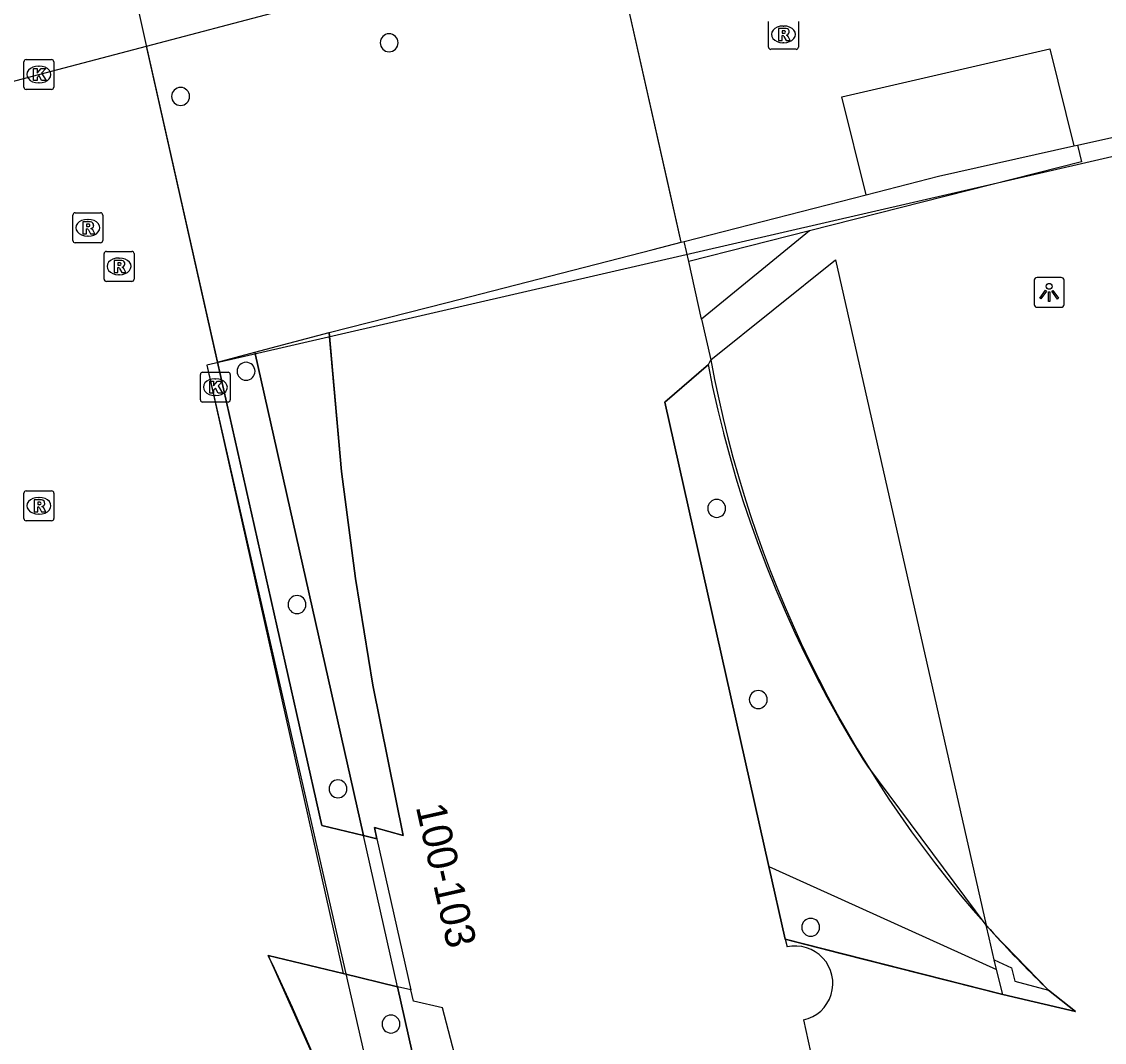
# Model space of a CAD drawing. Extents: x 160806 to 161707, y 383697 to 384148.
# Drawn here: x 161397.72 to 161433.94, y 383896.21 to 383930.37 of the extents above; entities that cross this region are included whole.
import ezdxf

# ---------------------------------------------------------------- set-up
doc = ezdxf.new("R2010")
doc.units = 0
for name, color, linetype in [('IMGEO_Hek', 7, 'Continuous'), ('IMGEO_Kolk', 7, 'Continuous'), ('IMGEO_Lichtpunt', 7, 'Continuous'), ('IMGEO_Lijnafwatering', 7, 'Continuous'), ('IMGEO_Muur', 7, 'Continuous'), ('IMGEO_OVBaan_gesloten', 7, 'Continuous'), ('IMGEO_Pand', 7, 'Continuous'), ('IMGEO_Pand_nummerreeks', 7, 'Continuous'), ('IMGEO_Pand_overbouw', 7, 'Continuous'), ('IMGEO_Rijbaan_lokaal_open', 7, 'Continuous'), ('IMGEO_Rioolput', 7, 'Continuous'), ('IMGEO_Voetpad_open', 7, 'Continuous')]:
    doc.layers.add(name, color=color, linetype=linetype)

msp = doc.modelspace()

# ---------------------------------------------------------------- linework, layer by layer
at = {"layer": 'IMGEO_Hek'}
for points in [[(161405.527, 383919.308), (161408.013, 383919.96)], [(161409.16, 383903.134), (161405.527, 383919.308)], [(161410.296, 383898.071), (161409.16, 383903.134)], [(161418.7, 383860.601), (161410.296, 383898.071)]]:
    msp.add_lwpolyline(points, dxfattribs=at)
at = {"layer": 'IMGEO_Kolk'}
for p, q in [((161397.8, 383928.172), (161397.8, 383929.024)), ((161397.875, 383929.098), (161398.727, 383929.098)), ((161398.288, 383928.878), (161398.313, 383928.878)), ((161398.801, 383929.024), (161398.801, 383928.172)), ((161398.311, 383928.318), (161398.286, 383928.318)), ((161398.727, 383928.098), (161397.875, 383928.098)), ((161403.703, 383917.71), (161403.703, 383918.562)), ((161403.778, 383918.636), (161404.63, 383918.636)), ((161404.191, 383918.416), (161404.216, 383918.416)), ((161404.704, 383918.562), (161404.704, 383917.71)), ((161404.63, 383917.636), (161403.778, 383917.636)), ((161404.214, 383917.856), (161404.189, 383917.856))]:
    msp.add_line(p, q, dxfattribs=at)
for points in [[(161397.8, 383928.172), (161397.8, 383929.024)], [(161397.875, 383929.098), (161398.727, 383929.098)], [(161398.801, 383929.024), (161398.801, 383928.172)], [(161398.121, 383928.798), (161398.244, 383928.798), (161398.244, 383928.647), (161398.374, 383928.798), (161398.538, 383928.798), (161398.392, 383928.647), (161398.545, 383928.398), (161398.393, 383928.398), (161398.308, 383928.562), (161398.244, 383928.495), (161398.244, 383928.398), (161398.121, 383928.398), (161398.121, 383928.798)], [(161398.727, 383928.098), (161397.875, 383928.098)], [(161403.703, 383917.71), (161403.703, 383918.562)], [(161403.778, 383918.636), (161404.63, 383918.636)], [(161404.704, 383918.562), (161404.704, 383917.71)], [(161404.024, 383918.336), (161404.147, 383918.336), (161404.147, 383918.185), (161404.277, 383918.336), (161404.441, 383918.336), (161404.295, 383918.185), (161404.448, 383917.936), (161404.296, 383917.936), (161404.211, 383918.1), (161404.147, 383918.033), (161404.147, 383917.936), (161404.024, 383917.936), (161404.024, 383918.336)], [(161404.63, 383917.636), (161403.778, 383917.636)]]:
    msp.add_lwpolyline(points, dxfattribs=at)
for centre, start, end in [((161397.877, 383929.022), 91.552, 178.448), ((161397.877, 383929.022), 91.552, 178.448), ((161398.725, 383929.022), 1.552, 88.448), ((161398.725, 383929.022), 1.552, 88.448), ((161397.877, 383928.174), 181.552, 268.448), ((161397.877, 383928.174), 181.552, 268.448), ((161398.725, 383928.174), 271.552, 358.448), ((161398.725, 383928.174), 271.552, 358.448), ((161403.78, 383918.56), 91.552, 178.448), ((161403.78, 383918.56), 91.552, 178.448), ((161404.628, 383918.56), 1.552, 88.448), ((161404.628, 383918.56), 1.552, 88.448), ((161403.78, 383917.712), 181.552, 268.448), ((161403.78, 383917.712), 181.552, 268.448), ((161404.628, 383917.712), 271.552, 358.448), ((161404.628, 383917.712), 271.552, 358.448)]:
    msp.add_arc(centre, 0.0765, start, end, dxfattribs=at)
for centre, major_axis, ratio, start_param, end_param in [((161398.287, 383928.598), (-0.387, 0.002), 0.722429, 4.712389, 7.853982), ((161398.312, 383928.598), (-0.39, 0.002), 0.717154, 1.570796, 4.712389), ((161404.19, 383918.136), (-0.387, 0.002), 0.722429, 4.712389, 7.853982), ((161404.215, 383918.136), (-0.39, 0.002), 0.717154, 1.570796, 4.712389)]:
    msp.add_ellipse(centre, major_axis=major_axis, ratio=ratio, start_param=start_param, end_param=end_param, dxfattribs=at)
at = {"layer": 'IMGEO_Lichtpunt'}
for p, q in [((161431.595, 383921.712), (161431.595, 383920.905)), ((161431.595, 383921.712), (161431.595, 383920.905)), ((161432.497, 383921.807), (161431.689, 383921.807)), ((161432.497, 383921.807), (161431.689, 383921.807)), ((161432.591, 383920.905), (161432.591, 383921.712)), ((161432.591, 383920.905), (161432.591, 383921.712)), ((161431.689, 383920.811), (161432.497, 383920.811)), ((161431.689, 383920.811), (161432.497, 383920.811))]:
    msp.add_line(p, q, dxfattribs=at)
for points in [[(161431.969, 383921.376), (161432.008, 383921.348), (161431.82, 383921.086), (161431.782, 383921.113), (161431.969, 383921.376)], [(161432.071, 383921.328), (161432.118, 383921.328), (161432.118, 383921.006), (161432.071, 383921.006), (161432.071, 383921.328)], [(161432.181, 383921.348), (161432.219, 383921.375), (161432.406, 383921.113), (161432.367, 383921.085), (161432.181, 383921.348)]]:
    msp.add_lwpolyline(points, dxfattribs=at)
msp.add_circle((161432.094, 383921.51), 0.0994, dxfattribs=at)
for centre, start, end in [((161431.689, 383921.712), 90, 180), ((161431.689, 383921.712), 90, 180), ((161432.497, 383921.712), 0, 90), ((161432.497, 383921.712), 0, 90), ((161431.689, 383920.905), 180, 270), ((161431.689, 383920.905), 180, 270), ((161432.497, 383920.905), 270, 0), ((161432.497, 383920.905), 270, 360)]:
    msp.add_arc(centre, 0.0946, start, end, dxfattribs=at)
at = {"layer": 'IMGEO_Lijnafwatering'}
msp.add_lwpolyline([(161403.923, 383918.874), (161408.481, 383898.51)], dxfattribs=at)
at = {"layer": 'IMGEO_Muur'}
for points in [[(161433.038, 383926.234), (161439.383, 383927.651)], [(161433.038, 383926.234), (161433.18, 383925.675), (161424.076, 383923.368)], [(161425.968, 383924.573), (161428.39, 383925.195), (161432.923, 383926.208)], [(161432.923, 383926.208), (161433.038, 383926.234)], [(161419.888, 383923.011), (161425.968, 383924.573)], [(161424.076, 383923.368), (161420.037, 383922.345)]]:
    msp.add_lwpolyline(points, dxfattribs=at)
at = {"layer": 'IMGEO_OVBaan_gesloten'}
for points in [[(161401.899, 383929.545), (161406.303, 383930.704), (161406.292, 383930.768), (161411.273, 383932.069), (161417.389, 383933.655)], [(161396.1, 383928.014), (161398.301, 383928.598), (161401.899, 383929.545)]]:
    msp.add_lwpolyline(points, dxfattribs=at)
at = {"layer": 'IMGEO_Pand'}
for points in [[(161408.013, 383919.96), (161411.952, 383920.972), (161418.849, 383922.744), (161419.786, 383922.985)], [(161419.786, 383922.985), (161419.888, 383923.011)], [(161420.037, 383922.345), (161419.888, 383923.011)], [(161420.469, 383920.416), (161420.037, 383922.345)], [(161420.469, 383920.416), (161420.775, 383919.046)], [(161408.013, 383919.96), (161408.426, 383915.311), (161408.889, 383911.729), (161409.47, 383908.166), (161410.484, 383903.138), (161409.523, 383903.401), (161409.607, 383903.025)], [(161422.721, 383902.1), (161419.234, 383917.635), (161420.694, 383918.894), (161420.775, 383919.046)], [(161409.607, 383903.025), (161410.742, 383897.964)], [(161423.268, 383899.662), (161422.721, 383902.1)], [(161423.268, 383899.662), (161423.327, 383899.403)], [(161424.012, 383864.925), (161421.322, 383870.26), (161418.342, 383876.968), (161415.742, 383883.762), (161414.609, 383887.201), (161413.557, 383890.652), (161411.798, 383897.366), (161410.827, 383897.586), (161410.742, 383897.964)], [(161423.875, 383896.96), (161424.112, 383895.898)]]:
    msp.add_lwpolyline(points, dxfattribs=at)
for centre, radius, start, end in [((161410.016, 383929.66), 0.3, 90, 270), ((161410.016, 383929.66), 0.3, 270, 90), ((161403.04, 383927.864), 0.3, 90, 270), ((161403.04, 383927.864), 0.3, 270, 90), ((161405.23, 383918.667), 0.3, 90, 270), ((161405.23, 383918.667), 0.3, 270, 90), ((161420.973, 383914.079), 0.3, 90, 270), ((161420.973, 383914.079), 0.3, 270, 90), ((161406.935, 383910.86), 0.3, 90, 270), ((161406.935, 383910.86), 0.3, 270, 90), ((161422.364, 383907.682), 0.3, 90, 270), ((161422.364, 383907.682), 0.3, 270, 90), ((161408.305, 383904.694), 0.3, 90, 270), ((161408.305, 383904.694), 0.3, 270, 90), ((161424.117, 383900.061), 0.3, 90, 270), ((161424.117, 383900.061), 0.3, 270, 90), ((161423.607, 383898.183), 1.252, 282.3385, 102.9475), ((161410.078, 383896.824), 0.3, 90, 270), ((161410.078, 383896.824), 0.3, 270, 90)]:
    msp.add_arc(centre, radius, start, end, dxfattribs=at)
at = {"layer": 'IMGEO_Pand_overbouw'}
for points in [[(161576.544, 383863.524), (161556.299, 383953.974), (161403.923, 383918.874), (161417.58, 383859.039), (161456.542, 383836.683)], [(161410.484, 383903.138), (161409.47, 383908.166), (161408.889, 383911.729), (161408.426, 383915.311), (161408.026, 383919.819), (161408.013, 383919.96), (161411.952, 383920.972), (161418.849, 383922.744), (161419.786, 383922.985), (161419.437, 383924.536), (161417.522, 383933.062), (161417.086, 383935.004), (161401.461, 383931.49), (161401.894, 383929.568), (161407.767, 383903.471), (161409.16, 383903.134), (161409.607, 383903.025), (161409.523, 383903.401)], [(161432.972, 383897.242), (161432.074, 383897.956), (161430.247, 383899.844), (161429.992, 383900.129), (161426.025, 383905.451), (161425.874, 383905.688), (161425.459, 383906.371), (161425.058, 383907.061), (161424.671, 383907.76), (161424.299, 383908.467), (161423.941, 383909.18), (161423.598, 383909.9), (161423.271, 383910.627), (161422.958, 383911.359), (161422.661, 383912.097), (161422.38, 383912.839), (161422.114, 383913.586), (161421.863, 383914.337), (161421.629, 383915.091), (161421.41, 383915.848), (161421.215, 383916.58), (161421.208, 383916.607), (161421.021, 383917.368), (161420.849, 383918.131), (161420.694, 383918.894), (161419.234, 383917.635), (161422.721, 383902.1), (161423.268, 383899.662), (161425.13, 383899.181), (161430.54, 383897.812)], [(161405.973, 383899.115), (161408.052, 383894.445), (161409.909, 383889.683), (161411.541, 383884.838), (161412.522, 383881.497), (161413.685, 383876.957), (161417.567, 383859.679), (161418.7, 383860.601), (161424.012, 383864.925), (161421.322, 383870.26), (161418.342, 383876.968), (161415.742, 383883.762), (161414.609, 383887.201), (161413.557, 383890.652), (161411.798, 383897.366), (161410.827, 383897.586), (161410.742, 383897.964), (161410.296, 383898.071), (161408.481, 383898.51)]]:
    msp.add_lwpolyline(points, close=True, dxfattribs=at)
at = {"layer": 'IMGEO_Rijbaan_lokaal_open'}
for points in [[(161419.786, 383922.985), (161417.522, 383933.062), (161417.389, 383933.655)], [(161404.279, 383918.971), (161401.899, 383929.545)], [(161425.968, 383924.573), (161425.161, 383927.855), (161432.12, 383929.454), (161432.923, 383926.208)], [(161433.038, 383926.234), (161439.383, 383927.651)], [(161405.527, 383919.308), (161408.013, 383919.96)], [(161404.279, 383918.971), (161405.527, 383919.308)], [(161409.16, 383903.134), (161407.767, 383903.471), (161404.279, 383918.971)], [(161410.296, 383898.071), (161409.16, 383903.134)], [(161405.973, 383899.115), (161408.481, 383898.51), (161410.296, 383898.071)]]:
    msp.add_lwpolyline(points, dxfattribs=at)
msp.add_arc((161307.805, 383852.606), 108.628, 17.2609, 25.35045, dxfattribs=at)
at = {"layer": 'IMGEO_Rioolput'}
for p, q in [((161422.704, 383929.515), (161422.704, 383930.367)), ((161423.705, 383930.367), (161423.705, 383929.515)), ((161423.192, 383930.221), (161423.217, 383930.221)), ((161423.215, 383929.661), (161423.19, 383929.661)), ((161423.631, 383929.441), (161422.779, 383929.441)), ((161399.437, 383923.044), (161399.437, 383923.896)), ((161399.512, 383923.97), (161400.364, 383923.97)), ((161400.438, 383923.896), (161400.438, 383923.044)), ((161399.925, 383923.75), (161399.95, 383923.75)), ((161399.948, 383923.19), (161399.923, 383923.19)), ((161400.364, 383922.97), (161399.512, 383922.97)), ((161400.482, 383921.751), (161400.482, 383922.603)), ((161400.557, 383922.677), (161401.409, 383922.677)), ((161400.97, 383922.457), (161400.995, 383922.457)), ((161401.483, 383922.603), (161401.483, 383921.751)), ((161401.409, 383921.677), (161400.557, 383921.677)), ((161400.993, 383921.897), (161400.968, 383921.897)), ((161397.801, 383913.74), (161397.801, 383914.592)), ((161397.876, 383914.666), (161398.728, 383914.666)), ((161398.289, 383914.446), (161398.314, 383914.446)), ((161398.802, 383914.592), (161398.802, 383913.74)), ((161398.728, 383913.666), (161397.876, 383913.666)), ((161398.312, 383913.886), (161398.287, 383913.886))]:
    msp.add_line(p, q, dxfattribs=at)
for points in [[(161422.704, 383929.515), (161422.704, 383930.367)], [(161423.705, 383930.367), (161423.705, 383929.515)], [(161423.293, 383930.139), (161423.041, 383930.141), (161423.041, 383929.741)], [(161423.219, 383930.06), (161423.165, 383930.06), (161423.165, 383929.979)], [(161423.165, 383929.979), (161423.217, 383929.979)], [(161423.041, 383929.741), (161423.165, 383929.741), (161423.165, 383929.903), (161423.176, 383929.903)], [(161423.223, 383929.874), (161423.294, 383929.741), (161423.434, 383929.741), (161423.369, 383929.867)], [(161423.631, 383929.441), (161422.779, 383929.441)], [(161399.437, 383923.044), (161399.437, 383923.896)], [(161399.512, 383923.97), (161400.364, 383923.97)], [(161400.438, 383923.896), (161400.438, 383923.044)], [(161400.026, 383923.668), (161399.774, 383923.67), (161399.774, 383923.27)], [(161399.774, 383923.27), (161399.898, 383923.27), (161399.898, 383923.432), (161399.909, 383923.432)], [(161399.952, 383923.589), (161399.898, 383923.589), (161399.898, 383923.508)], [(161399.898, 383923.508), (161399.95, 383923.508)], [(161399.956, 383923.403), (161400.027, 383923.27), (161400.167, 383923.27), (161400.102, 383923.396)], [(161400.364, 383922.97), (161399.512, 383922.97)], [(161400.482, 383921.751), (161400.482, 383922.603)], [(161400.557, 383922.677), (161401.409, 383922.677)], [(161401.071, 383922.375), (161400.819, 383922.377), (161400.819, 383921.977)], [(161401.483, 383922.603), (161401.483, 383921.751)], [(161400.819, 383921.977), (161400.943, 383921.977), (161400.943, 383922.139), (161400.954, 383922.139)], [(161400.997, 383922.296), (161400.943, 383922.296), (161400.943, 383922.215)], [(161400.943, 383922.215), (161400.995, 383922.215)], [(161401.001, 383922.11), (161401.072, 383921.977), (161401.212, 383921.977), (161401.147, 383922.103)], [(161401.409, 383921.677), (161400.557, 383921.677)], [(161397.801, 383913.74), (161397.801, 383914.592)], [(161397.876, 383914.666), (161398.728, 383914.666)], [(161398.802, 383914.592), (161398.802, 383913.74)], [(161398.39, 383914.364), (161398.138, 383914.366), (161398.138, 383913.966)], [(161398.138, 383913.966), (161398.262, 383913.966), (161398.262, 383914.128), (161398.273, 383914.128)], [(161398.316, 383914.285), (161398.262, 383914.285), (161398.262, 383914.204)], [(161398.262, 383914.204), (161398.314, 383914.204)], [(161398.32, 383914.099), (161398.391, 383913.966), (161398.531, 383913.966), (161398.466, 383914.092)], [(161398.728, 383913.666), (161397.876, 383913.666)]]:
    msp.add_lwpolyline(points, dxfattribs=at)
for centre, radius, start, end in [((161423.201, 383930.168), 0.19, 274.7715, 282.9687), ((161423.225, 383929.964), 0.0964, 77.0061, 93.1865), ((161423.239, 383930.021), 0.0378, 276.6634, 79.6772), ((161423.292, 383930.029), 0.109, 350.3612, 89.416), ((161423.29, 383930.029), 0.112, 277.5842, 350.9817), ((161423.175, 383929.85), 0.0533, 26.0293, 88.6989), ((161423.274, 383929.814), 0.108, 29.5134, 73.7905), ((161422.781, 383929.517), 0.0765, 181.552, 268.448), ((161422.781, 383929.517), 0.0765, 181.552, 268.448), ((161423.629, 383929.517), 0.0765, 271.552, 358.448), ((161423.629, 383929.517), 0.0765, 271.552, 358.448), ((161399.514, 383923.894), 0.0765, 91.552, 178.448), ((161399.514, 383923.894), 0.0765, 91.552, 178.448), ((161400.362, 383923.894), 0.0765, 1.552, 88.448), ((161400.362, 383923.894), 0.0765, 1.552, 88.448), ((161399.908, 383923.379), 0.0533, 26.0293, 88.6989), ((161399.934, 383923.697), 0.19, 274.7715, 282.9687), ((161399.958, 383923.493), 0.0964, 77.0061, 93.1865), ((161399.972, 383923.55), 0.0378, 276.6634, 79.6772), ((161400.025, 383923.558), 0.109, 350.3612, 89.416), ((161400.023, 383923.558), 0.112, 277.5842, 350.9817), ((161400.007, 383923.343), 0.108, 29.5134, 73.7905), ((161399.514, 383923.046), 0.0765, 181.552, 268.448), ((161399.514, 383923.046), 0.0765, 181.552, 268.448), ((161400.362, 383923.046), 0.0765, 271.552, 358.448), ((161400.362, 383923.046), 0.0765, 271.552, 358.448), ((161400.559, 383922.601), 0.0765, 91.552, 178.448), ((161400.559, 383922.601), 0.0765, 91.552, 178.448), ((161401.07, 383922.265), 0.109, 350.3612, 89.416), ((161401.407, 383922.601), 0.0765, 1.552, 88.448), ((161401.407, 383922.601), 0.0765, 1.552, 88.448), ((161400.953, 383922.086), 0.0533, 26.0293, 88.6989), ((161400.979, 383922.404), 0.19, 274.7715, 282.9687), ((161401.003, 383922.2), 0.0964, 77.0061, 93.1865), ((161401.017, 383922.257), 0.0378, 276.6634, 79.6772), ((161401.068, 383922.265), 0.112, 277.5842, 350.9817), ((161401.052, 383922.05), 0.108, 29.5134, 73.7905), ((161400.559, 383921.753), 0.0765, 181.552, 268.448), ((161400.559, 383921.753), 0.0765, 181.552, 268.448), ((161401.407, 383921.753), 0.0765, 271.552, 358.448), ((161401.407, 383921.753), 0.0765, 271.552, 358.448), ((161397.878, 383914.59), 0.0765, 91.552, 178.448), ((161397.878, 383914.59), 0.0765, 91.552, 178.448), ((161398.726, 383914.59), 0.0765, 1.552, 88.448), ((161398.726, 383914.59), 0.0765, 1.552, 88.448), ((161398.272, 383914.075), 0.0533, 26.0293, 88.6989), ((161398.298, 383914.393), 0.19, 274.7715, 282.9687), ((161398.322, 383914.189), 0.0964, 77.0061, 93.1865), ((161398.336, 383914.246), 0.0378, 276.6634, 79.6772), ((161398.389, 383914.254), 0.109, 350.3612, 89.416), ((161398.387, 383914.254), 0.112, 277.5842, 350.9817), ((161398.371, 383914.039), 0.108, 29.5134, 73.7905), ((161397.878, 383913.742), 0.0765, 181.552, 268.448), ((161397.878, 383913.742), 0.0765, 181.552, 268.448), ((161398.726, 383913.742), 0.0765, 271.552, 358.448), ((161398.726, 383913.742), 0.0765, 271.552, 358.448)]:
    msp.add_arc(centre, radius, start, end, dxfattribs=at)
for centre, major_axis, ratio, start_param, end_param in [((161423.191, 383929.941), (-0.387, 0.002), 0.722429, 4.712389, 7.853982), ((161423.216, 383929.941), (-0.39, 0.002), 0.717154, 1.570796, 4.712389), ((161399.924, 383923.47), (-0.387, 0.002), 0.722429, 4.712389, 7.853982), ((161399.949, 383923.47), (-0.39, 0.002), 0.717154, 1.570796, 4.712389), ((161400.969, 383922.177), (-0.387, 0.002), 0.722429, 4.712389, 7.853982), ((161400.994, 383922.177), (-0.39, 0.002), 0.717154, 1.570796, 4.712389), ((161398.288, 383914.166), (-0.387, 0.002), 0.722429, 4.712389, 7.853982), ((161398.313, 383914.166), (-0.39, 0.002), 0.717154, 1.570796, 4.712389)]:
    msp.add_ellipse(centre, major_axis=major_axis, ratio=ratio, start_param=start_param, end_param=end_param, dxfattribs=at)
at = {"layer": 'IMGEO_Voetpad_open'}
for points in [[(161424.076, 383923.368), (161420.469, 383920.416)], [(161420.775, 383919.046), (161424.946, 383922.401), (161429.992, 383900.129)], [(161405.527, 383919.308), (161409.16, 383903.134)], [(161409.607, 383903.025), (161409.16, 383903.134)], [(161422.721, 383902.1), (161424.672, 383901.216), (161430.334, 383898.65)], [(161429.992, 383900.129), (161430.119, 383899.986), (161430.247, 383899.844)], [(161430.253, 383898.977), (161430.087, 383899.713), (161429.992, 383900.129)], [(161430.54, 383897.812), (161423.268, 383899.662)], [(161430.334, 383898.65), (161430.253, 383898.977)], [(161430.253, 383898.977), (161430.836, 383898.71), (161430.947, 383898.256), (161432.074, 383897.956)], [(161430.54, 383897.812), (161430.334, 383898.65)], [(161410.742, 383897.964), (161410.296, 383898.071)], [(161410.296, 383898.071), (161418.7, 383860.601)], [(161432.074, 383897.956), (161432.972, 383897.242), (161430.54, 383897.812)]]:
    msp.add_lwpolyline(points, dxfattribs=at)
for centre, radius, start, end in [((161459.294, 383926.11), 39.161, 190.3917, 221.5621), ((161459.898, 383926.709), 40.012, 222.1779, 225.9407)]:
    msp.add_arc(centre, radius, start, end, dxfattribs=at)

# ---------------------------------------------------------------- texts
at = {"layer": 'IMGEO_Pand_nummerreeks'}
msp.add_text('100-103', height=1, rotation=282.6392, dxfattribs=at).set_placement((161410.905, 383904.094))

doc.saveas('drawing.dxf')
